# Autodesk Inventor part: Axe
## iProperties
Shininess: 20.0
Angle Display Precision: 2
Document Length Units: 11269
Document Angle Units: 11279
Document Time Units: 11290
Document Mass Units: 11283
Document Length Units Precision: 3
Document Angle Units Precision: 2
Created: 2002-09
Part Number: Axe
Material: Par défaut
Document SubType Name: Modélisation
Designer: administrateur
Density: 0.0
Volumn: 0.0
Area: 0.0
PropertySet Name: Model Information
Control State: 0
Master: False
Checked Out: False
Author: administrateur
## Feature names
1. Extrusion1
2. Extrusion2
3. Extrusion3
4. Chanfrein1 [Chamfer]
5. Symétrie1 [Mirror]
